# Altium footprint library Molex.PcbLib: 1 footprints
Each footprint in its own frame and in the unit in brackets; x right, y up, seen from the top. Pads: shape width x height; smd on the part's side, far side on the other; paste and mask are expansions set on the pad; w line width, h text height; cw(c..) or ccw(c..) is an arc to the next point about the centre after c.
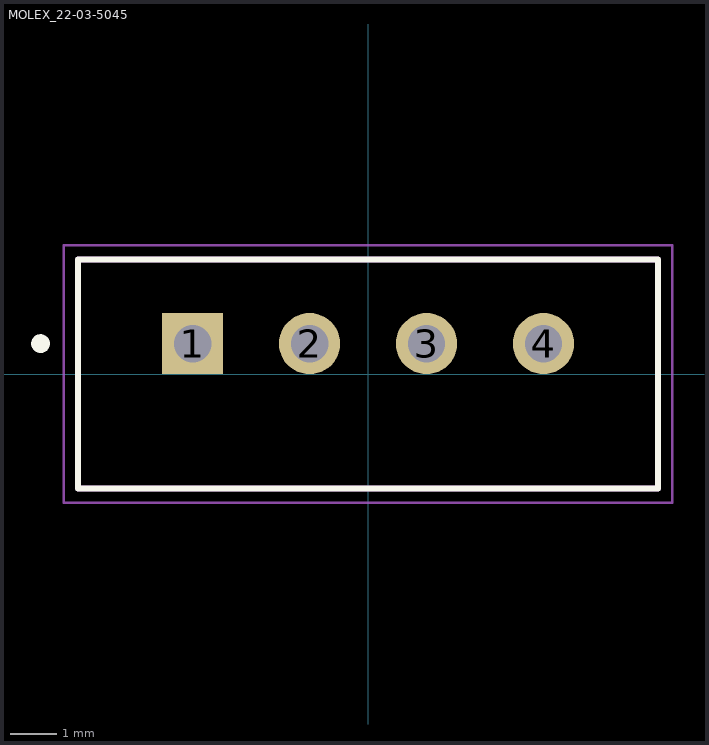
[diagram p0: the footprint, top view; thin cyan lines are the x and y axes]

## MOLEX_22-03-5045 [mm]
pads (4):
  rect 1.308x1.308 hole 0.8: 1(-3.75,0.65)
  round 1.308 hole 0.8: 2(-1.25,0.65) 3(1.25,0.65) 4(3.75,0.65)
Top Overlay:
  circle w0.2: c-7,0.65 r0.1
  lines w0.127: -6.2,-2.45 -6.2,2.45 6.2,2.45 6.2,-2.45 -6.2,-2.45
Mechanical 13:
  circle w0.2: c-3.75,0.65 r0.1
  lines w0.127: -6.2,-2.45 6.2,-2.45 6.2,2.45 -6.2,2.45 -6.2,-2.45
Mechanical 15:
  lines w0.05: -6.5,-2.75 6.5,-2.75 6.5,2.75 -6.5,2.75 -6.5,-2.75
